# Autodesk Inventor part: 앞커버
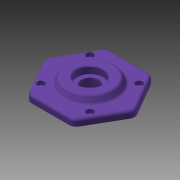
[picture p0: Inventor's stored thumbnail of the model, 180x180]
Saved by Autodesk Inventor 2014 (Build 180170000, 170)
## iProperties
Created: 2013-02
Part Number: 앞커버
Document SubType Name: Modeling
Density: 1 g/cm^3
Material: 일반
Appearance: 보라색
Author: 한국산업디자인학원[gmhk.co.kr]
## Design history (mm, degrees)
sketch "스케치1" dims "d37" = 105
  geometry: L1 (28.559, 41.466)-(50.191, 4); L2 (50.191, -4)-(28.559, -41.466); L3 (21.631, -45.466)-(-21.631, -45.466); L4 (-28.559, -41.466)-(-50.191, -4); L5 (-50.191, 4)-(-28.559, 41.466); L6 (-21.631, 45.466)-(21.631, 45.466); C1 r 30 at (0, 0); A1 r 8 centre (-43.262, 0) between (-50.191, 4) and (-50.191, -4); A2 r 8 centre (-21.631, 37.466) between (-21.631, 45.466) and (-28.559, 41.466); A3 r 8 centre (21.631, 37.466) between (28.559, 41.466) and (21.631, 45.466); A4 r 8 centre (43.262, 0) between (50.191, -4) and (50.191, 4); A5 r 8 centre (21.631, -37.466) between (21.631, -45.466) and (28.559, -41.466); A6 r 8 centre (-21.631, -37.466) between (-28.559, -41.466) and (-21.631, -45.466); 9 further points
  constraints: 12 end point, 12 point on circle, 12 point on line, 12 tangent, 7 centre point, 5 equal radius, 3 coincident, 1 horizontal, 16 other
  dimensions: "d40" = 8 radius of A1; "d41" = 60 diameter of C1
extrude "돌출1" new body sketch "스케치1" distance "d0" = 8; taper "d1" = 0 deg
sketch "스케치2"
  geometry: C1 r 30 at (0, 0); 1 further point
  constraints: 1 centre point, 1 coincident
  dimensions: "d2" = 60 diameter of C1
extrude "돌출2" join sketch "스케치2" distance "d3" = 7; taper "d4" = -30 deg
hole "구멍1" diameter "d7" = 20; stored, may be unused: countersink angle "d11" = 90 deg, drill point angle "d13" = 118 deg; dims "d8" = 6, "d9" = 30, "d10" = 8.3, "d12" = 20, "d52" = 10, "d53" = 10
sketch "스케치3"
  geometry: L1 (-28.284, 28.284)-(0, 0); L2 (0, 0)-(0, 40); L3 (0, 0)-(28.284, 28.284); L4 (0, 0)-(28.284, -28.284); L5 (0, 0)-(-28.284, -28.284); C1 r 1.621 at (28.284, 28.284); C2 r 1.621 at (-28.284, 28.284); C3 r 1.621 at (-28.284, -28.284); C4 r 1.621 at (28.284, -28.284); C5 r 10 at (0, 0) reference; A1 r 40 centre (0, 0) between (28.284, 28.284) and (-28.284, 28.284)
  constraints: 10 end point, 5 centre point, 3 perpendicular, 3 point on circle, 1 coincident, 1 vertical
  dimensions: "d48" = 80 diameter of A1; "d50" = 45 deg angle of L2 L1
hole "구멍2" sketch "스케치3" at (28.284, 28.284), (28.284, -28.284), (-28.284, -28.284), (-28.284, 28.284) diameter "d14" = 4.5; stored, may be unused: countersink angle "d18" = 90 deg, drill point angle "d20" = 118 deg; dims "d15" = 6, "d16" = 8, "d17" = 4.4, "d19" = 20
extrude "돌출3" join sketch "스케치1" distance "d21" = 12; taper "d22" = 0 deg
hole "구멍3" diameter "d25" = 30; stored, may be unused: countersink angle "d29" = 90 deg, drill point angle "d31" = 0 deg; dims "d26" = 6, "d27" = 40, "d28" = 12, "d30" = 15, "d42" = 10, "d43" = 10
fillet "모깎기1" dims "d32" = 3, "d33" = 0.3
chamfer "모따기1" distance "d34" = 1; stored, may be unused: second distance "d35" = 2, angle "d36" = 45 deg
chamfer "모따기2" distance "d44" = 1; stored, may be unused: second distance "d45" = 2, angle "d46" = 45 deg
fillet "모깎기2" dims "d47" = 3
fillet "모깎기3" dims "d54" = 0.6
node "솔리드1"
